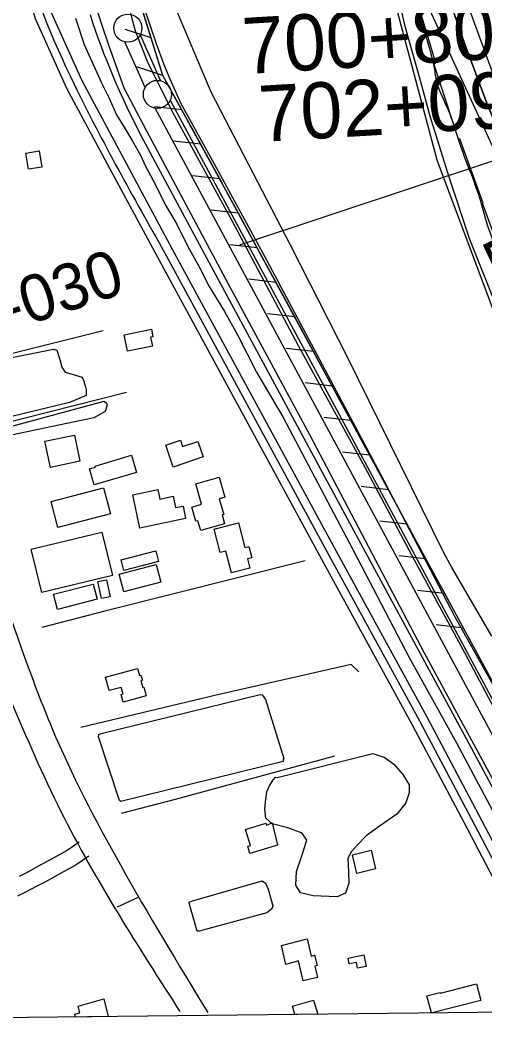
# Model space of a CAD drawing. Extents: x 3678539 to 3716648, y 451386 to 477139.
# Drawn here: x 3694736 to 3695563, y 456911 to 458713 of the extents above; entities that cross this region are included whole.
import ezdxf

# ---------------------------------------------------------------- set-up
doc = ezdxf.new("R2010")
doc.units = 0
for name, color, linetype in [('V-BLDG-OTLN', 7, 'Continuous'), ('V-FLOD-BASE', 7, 'Continuous'), ('V-GRID-FRAM', 7, 'Continuous'), ('V-LEVE-TOET', 7, 'Continuous'), ('V-RAIL-TRAK', 7, 'Continuous'), ('V-RIVR-EDGE', 7, 'Continuous'), ('V-RIVR-RANG', 7, 'Continuous'), ('V-RIVR-RANG-IDEN', 7, 'Continuous'), ('V-ROAD-CNTR', 7, 'Continuous'), ('V-RRAP-FSHR', 7, 'Continuous'), ('V-RRAP-RVMT', 7, 'Continuous'), ('V-SITE-VEGE', 7, 'Continuous'), ('V-SURV-IDEN', 7, 'Continuous'), ('V-SURV-LINE', 7, 'Continuous'), ('V-TOPO-DPTH', 7, 'Continuous'), ('V-TOPO-MINR', 7, 'Continuous'), ('V-TOPO-SHOR', 7, 'Continuous'), ('V-TOPO-WATR', 7, 'Continuous'), ('V-TOPO-WATR-IDEN', 7, 'Continuous')]:
    doc.layers.add(name, color=color, linetype=linetype)

msp = doc.modelspace()

# ---------------------------------------------------------------- linework, layer by layer
at = {"layer": 'V-BLDG-OTLN'}
for p, q in [((3695484.2, 456981.2), (3695548.6, 456997.5)), ((3695548.6, 456997.5), (3695556.1, 456967.8)), ((3694839.5, 456957.8), (3694885, 456971)), ((3694885, 456971), (3694893, 456939.3)), ((3695220.6, 456957.8), (3695258.4, 456968.7)), ((3695258.4, 456968.7), (3695265.7, 456943.6)), ((3695460.2, 456976.4), (3695483.9, 456982.4)), ((3695468, 456945.9), (3695460.2, 456976.4)), ((3695556.1, 456967.8), (3695469.7, 456945.9)), ((3695483.9, 456982.4), (3695484.2, 456981.2)), ((3694842.4, 456946), (3694839.5, 456957.8)), ((3695224.9, 456943.1), (3695220.6, 456957.8)), ((3694833.4, 456943.8), (3694842.4, 456946)), ((3694834.7, 456938.6), (3694833.4, 456943.8)), ((3694893, 456939.3), (3694834.7, 456938.6)), ((3695265.7, 456943.6), (3695224.9, 456943.1)), ((3695469.7, 456945.9), (3695468, 456945.9))]:
    msp.add_line(p, q, dxfattribs=at)
for points in [[(3694750.7, 458448.1), (3694746.2, 458476.8), (3694770.2, 458480.6), (3694774.7, 458451.8)], [(3694971.4, 458132.9), (3694926.9, 458124), (3694921, 458153.1), (3694969.8, 458163), (3694972.5, 458149.7), (3694968.2, 458148.8)], [(3694842.5, 457928), (3694790.1, 457917), (3694780.3, 457963.7), (3694832.7, 457974.7)], [(3695061.9, 457935.8), (3695008.3, 457917.7), (3694995.2, 457956.6), (3695021.5, 457965.5), (3695025.3, 457954.1), (3695052.6, 457963.3)], [(3694943.3, 457908.2), (3694867.6, 457886), (3694859.3, 457914.3), (3694870, 457917.5), (3694869.4, 457919.5), (3694934.3, 457938.6)], [(3695048.8, 457887.9), (3695090.2, 457899.7), (3695100.2, 457864.2), (3695090.5, 457861.4), (3695098.5, 457833.4), (3695095.5, 457832.6), (3695099.9, 457816.9), (3695057.4, 457804.9), (3695052.5, 457822.2), (3695048.9, 457821.2), (3695041.8, 457846.4), (3695059.1, 457851.4)], [(3694896.8, 457834.5), (3694803.4, 457810.2), (3694791.4, 457856.4), (3694884.7, 457880.7)], [(3694949, 457808.7), (3694936.4, 457868.3), (3694981, 457877.7), (3694984.6, 457860.8), (3695008.3, 457865.8), (3695012.6, 457845.5), (3695026, 457848.3), (3695030.7, 457826.1)], [(3695081.7, 457807.2), (3695125, 457818.2), (3695136, 457774.7), (3695143.3, 457776.5), (3695148.5, 457756.1), (3695140.8, 457754.2), (3695144.9, 457737.8), (3695112.1, 457729.5), (3695102.4, 457767.8), (3695092.3, 457765.3)], [(3694900.3, 457724.8), (3694774.5, 457694.3), (3694755.9, 457771.5), (3694881.6, 457801.9)], [(3694982.6, 457749.4), (3694920.7, 457733.6), (3694915.8, 457752.7), (3694977.7, 457768.5)], [(3694986.4, 457712.7), (3694920.6, 457695.7), (3694912.5, 457727), (3694978.3, 457744)], [(3694872.9, 457682.3), (3694802.4, 457664.1), (3694795.4, 457691.2), (3694865.9, 457709.4)], [(3694890, 457717.2), (3694896.2, 457686.8), (3694880.7, 457683.7), (3694874.6, 457714.1)], [(3694888, 457543.5), (3694945.1, 457559.3), (3694948.6, 457546.7), (3694951.2, 457547.4), (3694953.8, 457538.1), (3694951, 457537.3), (3694954.2, 457525.4), (3694956.2, 457526), (3694960.5, 457510.4), (3694919.5, 457499.1), (3694915.7, 457512.9), (3694919.3, 457513.9), (3694916.1, 457525.5), (3694894.6, 457519.6)], [(3695193.9, 457244.7), (3695145, 457229.8), (3695141.1, 457242.7), (3695145.8, 457244.1), (3695137.1, 457272.6), (3695173.5, 457283.7), (3695174.6, 457280.2), (3695184.6, 457284.1)], [(3695368.7, 457202.3), (3695335.6, 457194.1), (3695327.4, 457227.5), (3695360.6, 457235.6)], [(3695201.5, 457065.8), (3695246.8, 457077.6), (3695254.2, 457047.2), (3695260.1, 457048.6), (3695264.5, 457030.4), (3695260.4, 457029.4), (3695265.4, 457009.1), (3695240, 457002.9), (3695231.4, 457038.6), (3695209.2, 457032.3)], [(3695348, 457049), (3695351.9, 457028.7), (3695336.5, 457025.8), (3695334.6, 457035.9), (3695321.7, 457033.4), (3695319.7, 457043.6)]]:
    msp.add_lwpolyline(points, close=True, dxfattribs=at)
at = {"layer": 'V-FLOD-BASE'}
msp.add_lwpolyline([(3694928.9, 458739), (3694940.7, 458694.6), (3694963.6, 458637.5), (3695010.4, 458544.2), (3695113.4, 458355.4), (3695230.9, 458134.3), (3695349.6, 457917.8), (3695437.4, 457752.6), (3695527.4, 457586.2), (3695605.2, 457439.9), (3695678.3, 457309.2)], dxfattribs=at)
at = {"layer": 'V-GRID-FRAM'}
msp.add_lwpolyline([(3682569.5, 474981.5), (3714284.1, 475345.9), (3714501, 457164.6), (3682770.5, 456800), (3682569.5, 474981.5)], dxfattribs=at)
at = {"layer": 'V-LEVE-TOET'}
for points in [[(3694867.1, 458749.3), (3694881.2, 458706.1), (3694894.2, 458667.5), (3694905.4, 458636.4), (3694920.7, 458593.1), (3694961, 458516.5), (3695110.8, 458235), (3695251.1, 457975.9), (3695455.3, 457586.7), (3695609.1, 457303.4), (3695649.4, 457236.6), (3695814.5, 456949.9)], [(3694955.8, 458738.3), (3694978.3, 458671.7), (3694991.9, 458634.6), (3695002.5, 458608.6), (3695022, 458565.2), (3695074.2, 458470.9), (3695175.3, 458285.3), (3695377.4, 457904.8), (3695509.6, 457650.9), (3695696.3, 457319.6), (3695705.7, 457305.1), (3695710.4, 457297), (3695710.4, 457297), (3695716.8, 457283.1), (3695718.6, 457279.1), (3695733.3, 457245.5), (3695817.9, 457095.8), (3695920.2, 456951.1)]]:
    msp.add_lwpolyline(points, dxfattribs=at)
at = {"layer": 'V-RAIL-TRAK'}
msp.add_lwpolyline([(3694860.7, 458723.2), (3694865.1, 458709.3), (3694869.7, 458695.5), (3694874.5, 458681.8), (3694879.5, 458668.1), (3694884.7, 458654.5), (3694890.1, 458641), (3694897.4, 458623.2), (3694904.9, 458605.6), (3694912.6, 458588), (3694920.5, 458570.6), (3694928.6, 458553.2), (3694937, 458535.9), (3694945.5, 458518.8), (3694954.2, 458501.7), (3694963.1, 458484.7), (3695063.5, 458298.1), (3695229.1, 457990.9), (3695358.6, 457751.4), (3695534.2, 457427), (3695680.6, 457153.1)], dxfattribs=at)
at = {"layer": 'V-RIVR-EDGE'}
msp.add_spline([(3695003.3, 463492.6), (3695000.8, 463463), (3694999.1, 463436), (3694997.1, 463421.8), (3694996.2, 463401.2), (3694998.6, 463381.4), (3694999.7, 463362.4), (3694998.5, 463351.4), (3695000, 463303.7), (3695000.7, 463264.9), (3695002.7, 463245.9), (3695002.7, 463233.8), (3695001.8, 463214.8), (3694998.5, 463188.9), (3694994.8, 463169.9), (3694995.5, 463125.8), (3694996.7, 463096.3), (3694996.2, 463084.2), (3694995.4, 463074.1), (3694993.3, 463059.9), (3694993.7, 463043.3), (3694996.5, 463013), (3694998, 462984.7), (3694996.3, 462969.3), (3694992.6, 462945.9), (3694993, 462934.5), (3694992.5, 462900.2), (3694992.1, 462877.5), (3694994, 462832.2), (3694997.1, 462773.2), (3694999, 462727.9), (3694999.3, 462705.3), (3695007.6, 462630.4), (3695009.2, 462595.2), (3695009.5, 462562.1), (3695010.6, 462531.8), (3695012.8, 462442), (3695014.4, 462408), (3695013.5, 462364.3), (3695013, 462338.1), (3695013.3, 462295.6), (3695012.4, 462251.5), (3695013.1, 462227.3), (3695016.2, 462171.8), (3695021, 462140.3), (3695023.8, 462122.1), (3695022.9, 462103.1), (3695026.5, 462072.8), (3695026.8, 462056.6), (3695030, 462020.6), (3695034.8, 461994.3), (3695038.4, 461970.4), (3695039.1, 461952.6), (3695043.5, 461916.2), (3695045, 461889.9), (3695047.4, 461872.5), (3695060.9, 461747.2), (3695066.4, 461704.7), (3695073.6, 461658.2), (3695077.6, 461634.7), (3695082.7, 461596.3), (3695091.9, 461565.5), (3695097.2, 461547.7), (3695104, 461532.3), (3695112, 461510.9), (3695116.8, 461483.4), (3695118.8, 461467.6), (3695120.3, 461425.9), (3695123.5, 461389.9), (3695127.4, 461349.1), (3695129.3, 461320), (3695126.9, 461298.9), (3695117.5, 461263.8), (3695108.1, 461237.1), (3695101.2, 461218.5), (3695094.7, 461193.9), (3695089, 461178.5), (3695078.8, 461152.3), (3695074.3, 461138.9), (3695071.4, 461123.2), (3695071, 461103.4), (3695071.3, 461075.9), (3695071.3, 461049.6), (3695072.8, 461030.2), (3695076.4, 461011.6), (3695081.2, 460980.8), (3695086.8, 460964.6), (3695090.8, 460951.7), (3695103.3, 460933.9), (3695113.4, 460918.5), (3695125.5, 460890.1), (3695137.5, 460856.1), (3695146.7, 460824.6), (3695154.3, 460765.1), (3695158.9, 460696.4), (3695160.5, 460658.7), (3695162.8, 460604.6), (3695169.9, 460567.7), (3695176.8, 460541.4), (3695177.9, 460517.6), (3695180.2, 460471.1), (3695181, 460447.6), (3695189.3, 460380.5), (3695195.2, 460328.3), (3695203.2, 460275.7), (3695211.2, 460238.5), (3695232.7, 460118.3), (3695238.3, 460071), (3695245.5, 460035.4), (3695255.4, 459978), (3695257, 459946.4), (3695260.1, 459894.6), (3695262.4, 459856.6), (3695266.8, 459830.7), (3695276.4, 459794.7), (3695281.2, 459759.1), (3695287.1, 459711.8), (3695286.6, 459662.1), (3695294.2, 459614.3), (3695301.7, 459575.1), (3695314.1, 459521.3), (3695324.5, 459473.5), (3695329.7, 459440), (3695340.1, 459369.2), (3695346.8, 459309.7), (3695350.8, 459279.4), (3695355.1, 459253.1), (3695364.7, 459202.5), (3695369.5, 459170.6), (3695374.2, 459132.5), (3695378.2, 459096.1), (3695381.3, 459049.6), (3695387.6, 458986.9), (3695390.8, 458950.1), (3695396.4, 458919), (3695404.4, 458888.2), (3695414, 458854.6), (3695419.6, 458832.8), (3695445.6, 458734.5), (3695460.5, 458676.6), (3695472.9, 458628.4), (3695477.3, 458604.2), (3695497.8, 458553.6), (3695518.2, 458494.1), (3695541.5, 458431.7), (3695554.8, 458393.3), (3695569.6, 458342.7), (3695588.1, 458288.1), (3695592.9, 458266.6), (3695601.7, 458239.5), (3695614.6, 458208.4), (3695630.7, 458178), (3695639.9, 458153.7), (3695651.2, 458122.9), (3695659.2, 458096.6), (3695664, 458080), (3695671.6, 458058.6), (3695682.5, 458037.1), (3695696.6, 458011.6), (3695714.3, 457986.9), (3695728, 457970.7), (3695752.2, 457939.5), (3695776.4, 457905.1), (3695829.6, 457834.2), (3695873.5, 457775), (3695915, 457720.3), (3695953.3, 457672.1), (3695981.9, 457633.6), (3696006.1, 457603.3), (3696035.6, 457571.6), (3696055.7, 457549.4), (3696081.9, 457517.7), (3696109, 457483.3), (3696137.6, 457440.4), (3696153.3, 457416.5), (3696166.6, 457395.8), (3696192.8, 457363), (3696222.2, 457324.9), (3696262.5, 457276.7), (3696298, 457225.3), (3696365.3, 457130.5), (3696401.1, 457080.6), (3696434.2, 457035.7), (3696490.5, 456957.7)], degree=3, dxfattribs=at)
at = {"layer": 'V-RIVR-RANG'}
msp.add_line((3695127, 458313.2), (3696172.6, 458661.1), dxfattribs=at)
at = {"layer": 'V-ROAD-CNTR'}
for points in [[(3694802.4, 460669), (3694835.7, 460560.6), (3694869.2, 460452), (3694898.1, 460349.6), (3694922.9, 460244.7), (3694935.8, 460155.3), (3694938.9, 460065.9), (3694936.3, 459992.3), (3694927.8, 459918.6), (3694908.3, 459815.1), (3694881.8, 459713.4), (3694853.6, 459631.3), (3694825.1, 459550.3), (3694781.8, 459409.2), (3694746.7, 459265.9), (3694736.4, 459166.8), (3694736.4, 459066.8), (3694739.7, 458960.4), (3694753.9, 458855), (3694791.3, 458726.9), (3694845.8, 458605.8), (3694925.9, 458456.5), (3695006.3, 458306.8)], [(3694773.7, 460660.2), (3694807.1, 460551.7), (3694840.4, 460443.5), (3694869, 460342), (3694893.4, 460239.1), (3694905.8, 460152.7), (3694908.9, 460065.9), (3694906.4, 459994.5), (3694898.1, 459923.1), (3694879, 459821.7), (3694853.1, 459722.1), (3694825.2, 459641.2), (3694796.6, 459559.7), (3694752.8, 459417.2), (3694717, 459271), (3694706.4, 459168.3), (3694706.4, 459066.3), (3694709.7, 458957.9), (3694724.5, 458848.8), (3694763.1, 458716.5), (3694818.8, 458592.5), (3694899.5, 458442.4), (3694979.8, 458292.6)], [(3694993.1, 458299.7), (3695285.6, 457761), (3695447, 457466), (3695538.9, 457292.2), (3695611.1, 457154.4), (3695683.5, 457027), (3695726, 456959)], [(3695006.2, 458306.9), (3695298.8, 457768.2), (3695460.2, 457473.1), (3695552.1, 457299.2), (3695624.3, 457161.6), (3695696.4, 457034.7), (3695738.8, 456967)], [(3694979.9, 458292.6), (3695272.4, 457753.8), (3695433.7, 457458.9), (3695525.6, 457285.2), (3695598, 457147.3), (3695670.6, 457019.3), (3695713.3, 456951.1)], [(3694841.1, 457249.8), (3694819.9, 457235.2), (3694782.8, 457214.6), (3694766.7, 457205.8), (3694750.7, 457197.2), (3694734.5, 457188.8)], [(3694858.1, 457225), (3694835.7, 457209.7), (3694797.3, 457188.3), (3694781, 457179.4), (3694764.7, 457170.7), (3694748.2, 457162.1), (3694731.6, 457153.7)], [(3694909.5, 457135), (3694948, 457152.6)]]:
    msp.add_lwpolyline(points, dxfattribs=at)
for points in [[(3694788, 460664.6), (3694854.8, 460447.7), (3694908.2, 460241.9), (3694923.9, 460065.9), (3694912.9, 459920.9), (3694867.4, 459717.8), (3694810.9, 459555), (3694731.9, 459268.4), (3694721.4, 459066.6), (3694739.2, 458851.9), (3694832.3, 458599.2), (3694993.1, 458299.7)], [(3694641.7, 457877.7), (3694744.7, 457577.3), (3694792.5, 457453.3), (3694914.5, 457209.3), (3695069.9, 456946.6)], [(3694593.5, 457861.5), (3694661.7, 457647.7), (3694719.2, 457502.7), (3694808.7, 457304.6), (3695020.5, 456948.3)]]:
    msp.add_spline(points, degree=3, dxfattribs=at)
at = {"layer": 'V-RRAP-FSHR'}
for p, q in [((3694969.4, 458682), (3694922.9, 458696.8)), ((3694990.3, 458615.1), (3694943.7, 458630)), ((3695023.9, 458553.8), (3694975.4, 458559.1)), ((3695057.6, 458492.4), (3695009.1, 458497.7)), ((3695091.3, 458431.1), (3695042.8, 458436.4)), ((3695124.8, 458369.6), (3695076.3, 458375.1)), ((3695158.1, 458308), (3695109.6, 458313.6)), ((3695191.5, 458246.5), (3695143, 458252.1)), ((3695224.9, 458185), (3695176.3, 458190.5)), ((3695258.2, 458123.4), (3695209.7, 458129)), ((3695291.6, 458061.9), (3695243.1, 458067.5)), ((3695324.9, 458000.4), (3695276.4, 458005.9)), ((3695358.3, 457938.8), (3695309.8, 457944.4)), ((3695391.7, 457877.3), (3695343.1, 457882.8)), ((3695425, 457815.8), (3695376.5, 457821.3)), ((3695458.4, 457754.2), (3695409.9, 457759.8)), ((3695491.7, 457692.7), (3695443.2, 457698.2)), ((3695525.1, 457631.1), (3695476.6, 457636.7))]:
    msp.add_line(p, q, dxfattribs=at)
for points in [[(3695885.4, 456950.7), (3695644.2, 457411.5), (3695099.5, 458416.2), (3694990.3, 458614.9), (3694924.4, 458826.2), (3694902.4, 459031.9), (3694929.3, 459299.9), (3695020.8, 459615.1), (3695131.4, 459947.9), (3695139.7, 460021.6), (3695111.6, 460205), (3695042.2, 460419.6), (3695015.4, 460531.9), (3695015.9, 460690.5), (3694974.3, 460952.3), (3694839, 461769.5), (3694734.1, 462420.1), (3694690.3, 462677.6), (3694728.6, 462914.5), (3694833.9, 463120.6), (3694860.5, 463288.8), (3694907.2, 463779.2), (3694981.3, 464411.2)], [(3695002.5, 463782.6), (3694996.4, 463429.6), (3694990.1, 462766), (3695010.3, 462233.5), (3695040.8, 461859), (3695077.7, 461336.6), (3695066.2, 461216), (3695056.5, 460991.4), (3695138.2, 460666.7), (3695205.5, 460130.5), (3695369.1, 458872.1), (3695477.6, 458464.7), (3695628, 458064.1), (3695739.4, 457906.3), (3696072.8, 457458.1), (3696447.4, 456957.2)], [(3694969.4, 458682), (3694948.6, 458748.8)], [(3694990.3, 458615.1), (3694969.4, 458682)], [(3695023.9, 458553.8), (3694990.3, 458614.9), (3694990.3, 458615.1)], [(3695057.6, 458492.4), (3695023.9, 458553.8)], [(3695091.3, 458431.1), (3695057.6, 458492.4)], [(3695124.8, 458369.6), (3695099.5, 458416.2), (3695091.3, 458431.1)], [(3695158.1, 458308), (3695124.8, 458369.6)], [(3695191.5, 458246.5), (3695158.1, 458308)], [(3695224.9, 458185), (3695191.5, 458246.5)], [(3695258.2, 458123.4), (3695224.9, 458185)], [(3695291.6, 458061.9), (3695258.2, 458123.4)], [(3695324.9, 458000.4), (3695291.6, 458061.9)], [(3695358.3, 457938.8), (3695324.9, 458000.4)], [(3695391.7, 457877.3), (3695358.3, 457938.8)], [(3695425, 457815.8), (3695391.7, 457877.3)], [(3695458.4, 457754.2), (3695425, 457815.8)], [(3695491.7, 457692.7), (3695458.4, 457754.2)], [(3695540.1, 457603.4), (3695491.7, 457692.7)]]:
    msp.add_lwpolyline(points, dxfattribs=at)
at = {"layer": 'V-RRAP-RVMT'}
for p, q in [((3695475.7, 458636.9), (3695436, 458769.9)), ((3695472.5, 458635.8), (3695475.7, 458636.9)), ((3695516.4, 458501.4), (3695472.5, 458635.8)), ((3695518.5, 458502.1), (3695516.4, 458501.4)), ((3695560.2, 458387.8), (3695518.5, 458502.1)), ((3695558.8, 458387.3), (3695560.2, 458387.8)), ((3695600.9, 458272.2), (3695558.8, 458387.3))]:
    msp.add_line(p, q, dxfattribs=at)
at = {"layer": 'V-SITE-VEGE'}
for p, q in [((3695076.3, 458585), (3694987.5, 458795.9)), ((3695404.1, 458775.6), (3695419.9, 458704.8)), ((3695419.9, 458704.8), (3695448.9, 458604)), ((3695448.9, 458604), (3695464.7, 458545)), ((3695217.5, 458313), (3695076.3, 458585)), ((3695464.7, 458545), (3695499.1, 458434.2)), ((3695499.1, 458434.2), (3695535.8, 458323.4)), ((3695535.8, 458323.4), (3695625.9, 458096.6)), ((3695319.2, 458112.3), (3695217.5, 458313)), ((3695489.8, 457766.1), (3695319.2, 458112.3)), ((3695504.2, 457739), (3695489.8, 457766.1)), ((3695575.9, 457616.6), (3695504.2, 457739))]:
    msp.add_line(p, q, dxfattribs=at)
msp.add_lwpolyline([(3694703.3, 458109.3), (3694795.5, 458127.7), (3694801.5, 458126), (3694806.9, 458109.4), (3694810.5, 458095.8), (3694816.5, 458086.4), (3694834.9, 458081.2), (3694846.2, 458077.7), (3694849.2, 458070.7), (3694851.6, 458062.4), (3694853.4, 458055.3), (3694853.5, 458045.2), (3694824, 458032.6), (3694659.7, 457993.1)], dxfattribs=at)
for points in [[(3694670.5, 457976.6), (3694885.5, 458034.8), (3694890.3, 458030.7), (3694890.3, 458025.9), (3694887.4, 458016.5), (3694867.3, 458005.1), (3694671.7, 457964.2), (3694666.4, 457966.5), (3694666.4, 457968.3), (3694667.5, 457971.8)], [(3695204.5, 457393.6), (3694915.6, 457322.5), (3694913.2, 457324.3), (3694875.8, 457437.6), (3694876.3, 457441.8), (3694880.5, 457443.6), (3695163.5, 457512.9), (3695167, 457512.3), (3695173, 457504.1), (3695205.6, 457399), (3695204.5, 457397.2)], [(3695193.3, 457365), (3695363.7, 457408), (3695385, 457400.5), (3695401, 457388.8), (3695417.1, 457370.6), (3695428.5, 457351.8), (3695428.5, 457337.6), (3695422.8, 457319.8), (3695406.3, 457299.6), (3695375.8, 457278.2), (3695351.7, 457260.9), (3695336.4, 457245.4), (3695325.9, 457233), (3695319.4, 457221.1), (3695320.8, 457196.3), (3695320.9, 457176.8), (3695315.1, 457159), (3695300.4, 457152.5), (3695257.9, 457154.5), (3695234.8, 457159.7), (3695227, 457173.2), (3695228, 457197.5), (3695237.3, 457225.3), (3695246.6, 457253.7), (3695238.2, 457266), (3695212.8, 457275.3), (3695184.4, 457282.8), (3695173.1, 457292.8), (3695171.8, 457309.3), (3695173.4, 457326.5), (3695175.1, 457339.5), (3695179.8, 457350.1), (3695186.2, 457360.8), (3695190.3, 457365.6)], [(3695041, 457144.6), (3695166.8, 457180.9), (3695172.8, 457176.8), (3695177.6, 457166.2), (3695186.1, 457136.7), (3695184.3, 457131.3), (3695174.9, 457124.2), (3695055, 457091.4), (3695051.4, 457091.4), (3695036.9, 457141), (3695036.9, 457142.8)]]:
    msp.add_lwpolyline(points, close=True, dxfattribs=at)
at = {"layer": 'V-SURV-LINE'}
for points in [[(3694949.6, 458687), (3694986, 458605.6)], [(3694958.6, 458593.4), (3694922.2, 458674.8)], [(3695003.1, 458570.7), (3695730.6, 457217.7)], [(3695704.2, 457203.5), (3694976.7, 458556.5)]]:
    msp.add_lwpolyline(points, dxfattribs=at)
for centre in [(3694927.8, 458699.1), (3694980.4, 458581.2)]:
    msp.add_circle(centre, 25, dxfattribs=at)
at = {"layer": 'V-TOPO-DPTH'}
msp.add_lwpolyline([(3696514.6, 456957.9), (3695966, 457716.9), (3695955.6, 457732.2), (3695945.7, 457747.8), (3695936.8, 457764), (3695928.5, 457780.4), (3695657.5, 458356.1), (3695610.8, 458460.2), (3695566.8, 458565.3), (3695526.7, 458672.1), (3695489.3, 458779.8)], dxfattribs=at)
at = {"layer": 'V-TOPO-MINR'}
for points in [[(3695438.4, 458998.8), (3695574.2, 458625.9), (3695630.5, 458477.5), (3695689.4, 458330.1), (3695752.2, 458184.3), (3695817.5, 458039.7), (3695940.3, 457777.1), (3695946.5, 457764.7), (3695953.2, 457752.5), (3695960.6, 457740.8), (3695968.3, 457729.4), (3696352.5, 457197.4), (3696390.2, 457146.3), (3696428.7, 457095.8), (3696468.2, 457046.1), (3696508.4, 456997), (3696541, 456958.2)], [(3695443.7, 458777.9), (3695897.8, 457789.8), (3695910.9, 457761.9), (3695924.2, 457734.1), (3695937.9, 457706.6), (3695951.9, 457679.1), (3695966.4, 457651.2), (3695988.7, 457610.4), (3696012.1, 457570.3), (3696037.2, 457531.2), (3696063.5, 457492.9), (3696447.9, 456957.2)]]:
    msp.add_lwpolyline(points, dxfattribs=at)
at = {"layer": 'V-TOPO-SHOR'}
msp.add_line((3694925.6, 458050.5), (3694660.4, 457983.6), dxfattribs=at)
for points in [[(3694834.4, 458717.1), (3694850.3, 458669.9), (3694880.7, 458601.6), (3694894.1, 458575.7), (3694907.6, 458544.7), (3694923.3, 458520), (3694936.1, 458498.2), (3694950.1, 458472.9), (3694959.5, 458453.4), (3694972.3, 458429.3), (3694982.2, 458409.2), (3694995.1, 458383.9), (3695014.9, 458350), (3695034.7, 458310.4), (3695054, 458275.4), (3695072.7, 458239.2), (3695100, 458194.4), (3695122.8, 458153.1), (3695156.6, 458086.5), (3695203.8, 458007.3), (3695328.1, 457770.7), (3695428.5, 457578.9), (3695513, 457426.7), (3695586.5, 457288.3)], [(3694883.6, 458160.3), (3694631.6, 458097.6), (3694627, 458096.4)], [(3695243.4, 457750.6), (3694886.7, 457661.3), (3694775, 457632.3)], [(3695338.7, 457552.9), (3695325.4, 457566.1), (3695084.8, 457511.8), (3694844.2, 457454.1)], [(3695295.8, 457402.9), (3695012.2, 457325.6), (3694916.1, 457300.8)]]:
    msp.add_lwpolyline(points, dxfattribs=at)
at = {"layer": 'V-TOPO-WATR'}
msp.add_lwpolyline([(3695489.3, 458779.8), (3695526.7, 458672.1), (3695566.8, 458565.3), (3695610.8, 458460.2), (3695657.5, 458356.1), (3695928.5, 457780.4), (3695936.8, 457764), (3695945.7, 457747.8), (3695955.6, 457732.2), (3695966, 457716.9), (3696514.6, 456957.9)], dxfattribs=at)

# ---------------------------------------------------------------- texts
at = {"layer": 'V-RIVR-RANG-IDEN'}
msp.add_text('U-030', height=83, rotation=18.2623, dxfattribs=at).set_placement((3694639.3, 458134.1))
at = {"layer": 'V-SURV-IDEN'}
for s, rotation, p in [('700+80.6', 3.5324, (3695134.7, 458617.1)), ('702+09.8', 3.3468, (3695163.6, 458496.4))]:
    msp.add_text(s, height=100, rotation=rotation, dxfattribs=at).set_placement(p)
at = {"layer": 'V-TOPO-WATR-IDEN'}
msp.add_text('L.W.R.P.', height=83, rotation=295.2394, dxfattribs=at).set_placement((3695555.7, 458321.4))

doc.saveas('drawing.dxf')
